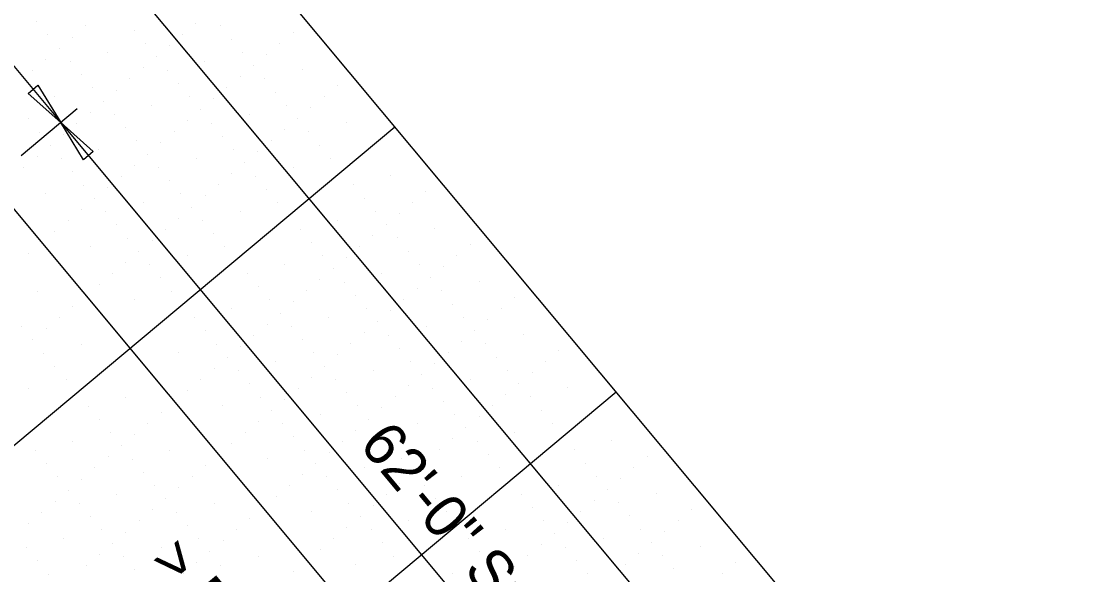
# Model space of a CAD drawing. Extents: x 2042995 to 2043795, y 305365 to 306249.
# Drawn here: x 2043429.3 to 2043490.7, y 305730.9 to 305763 of the extents above; entities that cross this region are included whole.
import ezdxf

# ---------------------------------------------------------------- set-up
doc = ezdxf.new("R2010")
doc.units = 0
for name, color, linetype in [('BR_AUTO DIMENSION', 7, 'Continuous'), ('BR_BORDER LINES', 7, 'Continuous'), ('BR_CONCRETE', 7, 'Continuous'), ('BR_GRID DOTS', 7, 'Continuous'), ('BR_GRID LINES', 7, 'Continuous'), ('BR_TEXT', 7, 'Continuous')]:
    doc.layers.add(name, color=color, linetype=linetype)

msp = doc.modelspace()

# ---------------------------------------------------------------- linework, layer by layer
at = {"layer": 'BR_AUTO DIMENSION'}
for p, q in [((2043319.917, 305903.59), (2043477.609, 305714.78)), ((2043353.357, 305850.739), (2043431.562, 305757.101)), ((2043429.275, 305755.192), (2043432.521, 305757.903)), ((2043431.562, 305757.101), (2043471.306, 305709.515))]:
    msp.add_line(p, q, dxfattribs=at)
for points in [[(2043430.247, 305759.261), (2043431.562, 305757.101), (2043429.672, 305758.78)], [(2043432.877, 305754.942), (2043431.562, 305757.101), (2043433.452, 305755.423)]]:
    msp.add_lwpolyline(points, close=True, dxfattribs=at)
at = {"layer": 'BR_BORDER LINES'}
msp.add_line((2043183.839, 306076.621), (2043615.462, 305559.826), dxfattribs=at)
at = {"layer": 'BR_CONCRETE'}
msp.add_spline([(2043139.109, 306017.548), (2043148.199, 306007.16), (2043160.233, 305993.368), (2043172.245, 305979.557), (2043184.234, 305965.727), (2043196.201, 305951.879), (2043208.145, 305938.012), (2043220.067, 305924.126), (2043231.966, 305910.221), (2043243.843, 305896.297), (2043255.698, 305882.355), (2043267.529, 305868.394), (2043279.339, 305854.414), (2043291.126, 305840.415), (2043302.89, 305826.398), (2043314.632, 305812.361), (2043326.352, 305798.306), (2043338.049, 305784.233), (2043349.724, 305770.14), (2043361.376, 305756.029), (2043373.005, 305741.899), (2043384.613, 305727.75), (2043396.197, 305713.582), (2043407.76, 305699.396), (2043419.299, 305685.191), (2043430.817, 305670.967), (2043442.311, 305656.724), (2043453.784, 305642.463), (2043465.234, 305628.182), (2043476.661, 305613.883), (2043488.066, 305599.566), (2043499.448, 305585.229), (2043510.808, 305570.874), (2043522.146, 305556.5), (2043533.461, 305542.107), (2043544.753, 305527.695), (2043547.219, 305524.543)], degree=3, dxfattribs=at)
at = {"layer": 'BR_GRID DOTS'}
for p, q in [((2043430.185, 305762.945), (2043430.185, 305762.945)), ((2043433.002, 305762.692), (2043433.002, 305762.692)), ((2043435.819, 305762.439), (2043435.819, 305762.439)), ((2043439.403, 305762.827), (2043439.403, 305762.827)), ((2043440.812, 305762.7), (2043440.812, 305762.7)), ((2043445.037, 305762.321), (2043445.037, 305762.321)), ((2043430.826, 305762.177), (2043430.826, 305762.177)), ((2043432.234, 305762.051), (2043432.234, 305762.051)), ((2043436.46, 305761.671), (2043436.46, 305761.671)), ((2043438.636, 305762.186), (2043438.636, 305762.186)), ((2043441.453, 305761.933), (2043441.453, 305761.933)), ((2043444.27, 305761.68), (2043444.27, 305761.68)), ((2043431.467, 305761.41), (2043431.467, 305761.41)), ((2043434.284, 305761.157), (2043434.284, 305761.157)), ((2043437.868, 305761.545), (2043437.868, 305761.545)), ((2043442.094, 305761.165), (2043442.094, 305761.165)), ((2043443.502, 305761.039), (2043443.502, 305761.039)), ((2043430.699, 305760.769), (2043430.699, 305760.769)), ((2043432.108, 305760.642), (2043432.108, 305760.642)), ((2043437.101, 305760.904), (2043437.101, 305760.904)), ((2043439.918, 305760.651), (2043439.918, 305760.651)), ((2043442.735, 305760.398), (2043442.735, 305760.398)), ((2043429.932, 305760.128), (2043429.932, 305760.128)), ((2043432.749, 305759.875), (2043432.749, 305759.875)), ((2043436.333, 305760.263), (2043436.333, 305760.263)), ((2043437.742, 305760.136), (2043437.742, 305760.136)), ((2043445.552, 305760.145), (2043445.552, 305760.145)), ((2043435.566, 305759.622), (2043435.566, 305759.622)), ((2043438.383, 305759.369), (2043438.383, 305759.369)), ((2043441.967, 305759.757), (2043441.967, 305759.757)), ((2043443.376, 305759.63), (2043443.376, 305759.63)), ((2043447.602, 305759.251), (2043447.602, 305759.251)), ((2043431.214, 305758.593), (2043431.214, 305758.593)), ((2043433.39, 305759.107), (2043433.39, 305759.107)), ((2043434.798, 305758.981), (2043434.798, 305758.981)), ((2043439.024, 305758.601), (2043439.024, 305758.601)), ((2043441.2, 305759.116), (2043441.2, 305759.116)), ((2043444.017, 305758.863), (2043444.017, 305758.863)), ((2043446.834, 305758.61), (2043446.834, 305758.61)), ((2043434.031, 305758.34), (2043434.031, 305758.34)), ((2043436.848, 305758.087), (2043436.848, 305758.087)), ((2043440.432, 305758.475), (2043440.432, 305758.475)), ((2043444.658, 305758.095), (2043444.658, 305758.095)), ((2043446.067, 305757.969), (2043446.067, 305757.969)), ((2043433.263, 305757.699), (2043433.263, 305757.699)), ((2043434.672, 305757.572), (2043434.672, 305757.572)), ((2043439.665, 305757.834), (2043439.665, 305757.834)), ((2043442.482, 305757.581), (2043442.482, 305757.581)), ((2043445.299, 305757.328), (2043445.299, 305757.328)), ((2043429.679, 305757.311), (2043429.679, 305757.311)), ((2043432.496, 305757.058), (2043432.496, 305757.058)), ((2043435.313, 305756.805), (2043435.313, 305756.805)), ((2043438.897, 305757.193), (2043438.897, 305757.193)), ((2043440.306, 305757.066), (2043440.306, 305757.066)), ((2043448.116, 305757.075), (2043448.116, 305757.075)), ((2043430.32, 305756.543), (2043430.32, 305756.543)), ((2043431.728, 305756.417), (2043431.728, 305756.417)), ((2043438.13, 305756.552), (2043438.13, 305756.552)), ((2043440.947, 305756.299), (2043440.947, 305756.299)), ((2043444.531, 305756.687), (2043444.531, 305756.687)), ((2043445.94, 305756.56), (2043445.94, 305756.56)), ((2043430.961, 305755.776), (2043430.961, 305755.776)), ((2043433.778, 305755.523), (2043433.778, 305755.523)), ((2043435.954, 305756.037), (2043435.954, 305756.037)), ((2043437.362, 305755.911), (2043437.362, 305755.911)), ((2043441.588, 305755.531), (2043441.588, 305755.531)), ((2043443.764, 305756.046), (2043443.764, 305756.046)), ((2043446.581, 305755.793), (2043446.581, 305755.793)), ((2043430.193, 305755.135), (2043430.193, 305755.135)), ((2043431.602, 305755.008), (2043431.602, 305755.008)), ((2043436.595, 305755.27), (2043436.595, 305755.27)), ((2043439.412, 305755.017), (2043439.412, 305755.017)), ((2043442.996, 305755.405), (2043442.996, 305755.405)), ((2043447.222, 305755.025), (2043447.222, 305755.025)), ((2043429.426, 305754.493), (2043429.426, 305754.493)), ((2043435.827, 305754.629), (2043435.827, 305754.629)), ((2043437.236, 305754.502), (2043437.236, 305754.502)), ((2043442.229, 305754.764), (2043442.229, 305754.764)), ((2043445.046, 305754.511), (2043445.046, 305754.511)), ((2043432.243, 305754.24), (2043432.243, 305754.24)), ((2043435.06, 305753.988), (2043435.06, 305753.988)), ((2043437.877, 305753.735), (2043437.877, 305753.735)), ((2043441.461, 305754.123), (2043441.461, 305754.123)), ((2043442.87, 305753.996), (2043442.87, 305753.996)), ((2043450.68, 305754.005), (2043450.68, 305754.005)), ((2043432.884, 305753.473), (2043432.884, 305753.473)), ((2043434.292, 305753.346), (2043434.292, 305753.346)), ((2043440.694, 305753.482), (2043440.694, 305753.482)), ((2043443.511, 305753.229), (2043443.511, 305753.229)), ((2043448.504, 305753.49), (2043448.504, 305753.49)), ((2043452.73, 305753.111), (2043452.73, 305753.111)), ((2043430.708, 305752.958), (2043430.708, 305752.958)), ((2043433.525, 305752.705), (2043433.525, 305752.705)), ((2043436.342, 305752.452), (2043436.342, 305752.452)), ((2043438.518, 305752.967), (2043438.518, 305752.967)), ((2043439.926, 305752.841), (2043439.926, 305752.841)), ((2043444.152, 305752.461), (2043444.152, 305752.461)), ((2043449.145, 305752.723), (2043449.145, 305752.723)), ((2043451.962, 305752.47), (2043451.962, 305752.47)), ((2043432.757, 305752.064), (2043432.757, 305752.064)), ((2043434.166, 305751.938), (2043434.166, 305751.938)), ((2043439.159, 305752.199), (2043439.159, 305752.199)), ((2043441.976, 305751.946), (2043441.976, 305751.946)), ((2043449.786, 305751.955), (2043449.786, 305751.955)), ((2043451.195, 305751.829), (2043451.195, 305751.829)), ((2043431.99, 305751.423), (2043431.99, 305751.423)), ((2043438.391, 305751.558), (2043438.391, 305751.558)), ((2043439.8, 305751.432), (2043439.8, 305751.432)), ((2043447.61, 305751.441), (2043447.61, 305751.441)), ((2043450.427, 305751.188), (2043450.427, 305751.188)), ((2043431.222, 305750.782), (2043431.222, 305750.782)), ((2043434.807, 305751.17), (2043434.807, 305751.17)), ((2043437.624, 305750.917), (2043437.624, 305750.917)), ((2043440.441, 305750.664), (2043440.441, 305750.664)), ((2043445.434, 305750.926), (2043445.434, 305750.926)), ((2043453.244, 305750.935), (2043453.244, 305750.935)), ((2043430.455, 305750.141), (2043430.455, 305750.141)), ((2043435.448, 305750.403), (2043435.448, 305750.403)), ((2043436.856, 305750.276), (2043436.856, 305750.276)), ((2043446.075, 305750.158), (2043446.075, 305750.158)), ((2043449.66, 305750.547), (2043449.66, 305750.547)), ((2043451.068, 305750.42), (2043451.068, 305750.42)), ((2043455.294, 305750.041), (2043455.294, 305750.041)), ((2043429.687, 305749.5), (2043429.687, 305749.5)), ((2043433.272, 305749.888), (2043433.272, 305749.888)), ((2043436.089, 305749.635), (2043436.089, 305749.635)), ((2043438.906, 305749.382), (2043438.906, 305749.382)), ((2043441.082, 305749.897), (2043441.082, 305749.897)), ((2043446.716, 305749.391), (2043446.716, 305749.391)), ((2043448.892, 305749.905), (2043448.892, 305749.905)), ((2043451.709, 305749.652), (2043451.709, 305749.652)), ((2043454.526, 305749.4), (2043454.526, 305749.4)), ((2043435.321, 305748.994), (2043435.321, 305748.994)), ((2043436.73, 305748.868), (2043436.73, 305748.868)), ((2043444.54, 305748.876), (2043444.54, 305748.876)), ((2043448.125, 305749.264), (2043448.125, 305749.264)), ((2043452.35, 305748.885), (2043452.35, 305748.885)), ((2043453.759, 305748.758), (2043453.759, 305748.758)), ((2043434.554, 305748.353), (2043434.554, 305748.353)), ((2043442.364, 305748.362), (2043442.364, 305748.362)), ((2043447.357, 305748.623), (2043447.357, 305748.623)), ((2043450.174, 305748.37), (2043450.174, 305748.37)), ((2043452.991, 305748.117), (2043452.991, 305748.117)), ((2043433.786, 305747.712), (2043433.786, 305747.712)), ((2043437.371, 305748.1), (2043437.371, 305748.1)), ((2043443.005, 305747.594), (2043443.005, 305747.594)), ((2043446.59, 305747.982), (2043446.59, 305747.982)), ((2043447.998, 305747.856), (2043447.998, 305747.856)), ((2043455.808, 305747.864), (2043455.808, 305747.864)), ((2043430.202, 305747.324), (2043430.202, 305747.324)), ((2043433.019, 305747.071), (2043433.019, 305747.071)), ((2043438.012, 305747.333), (2043438.012, 305747.333)), ((2043445.822, 305747.341), (2043445.822, 305747.341)), ((2043448.639, 305747.088), (2043448.639, 305747.088)), ((2043452.224, 305747.476), (2043452.224, 305747.476)), ((2043453.632, 305747.35), (2043453.632, 305747.35)), ((2043457.858, 305746.97), (2043457.858, 305746.97)), ((2043432.251, 305746.43), (2043432.251, 305746.43)), ((2043435.836, 305746.818), (2043435.836, 305746.818)), ((2043441.47, 305746.312), (2043441.47, 305746.312)), ((2043443.646, 305746.827), (2043443.646, 305746.827)), ((2043445.055, 305746.7), (2043445.055, 305746.7)), ((2043449.28, 305746.321), (2043449.28, 305746.321)), ((2043451.456, 305746.835), (2043451.456, 305746.835)), ((2043454.273, 305746.582), (2043454.273, 305746.582)), ((2043457.09, 305746.329), (2043457.09, 305746.329)), ((2043431.484, 305745.789), (2043431.484, 305745.789)), ((2043439.294, 305745.798), (2043439.294, 305745.798)), ((2043444.287, 305746.059), (2043444.287, 305746.059)), ((2043447.104, 305745.806), (2043447.104, 305745.806)), ((2043450.689, 305746.194), (2043450.689, 305746.194)), ((2043454.914, 305745.815), (2043454.914, 305745.815)), ((2043456.323, 305745.688), (2043456.323, 305745.688)), ((2043429.308, 305745.275), (2043429.308, 305745.275)), ((2043430.716, 305745.148), (2043430.716, 305745.148)), ((2043443.52, 305745.418), (2043443.52, 305745.418)), ((2043444.928, 305745.292), (2043444.928, 305745.292)), ((2043449.921, 305745.553), (2043449.921, 305745.553)), ((2043452.738, 305745.3), (2043452.738, 305745.3)), ((2043455.555, 305745.047), (2043455.555, 305745.047)), ((2043429.949, 305744.507), (2043429.949, 305744.507)), ((2043439.935, 305745.03), (2043439.935, 305745.03)), ((2043442.752, 305744.777), (2043442.752, 305744.777)), ((2043445.569, 305744.524), (2043445.569, 305744.524)), ((2043449.154, 305744.912), (2043449.154, 305744.912)), ((2043450.562, 305744.786), (2043450.562, 305744.786)), ((2043458.373, 305744.794), (2043458.373, 305744.794)), ((2043432.766, 305744.254), (2043432.766, 305744.254)), ((2043440.576, 305744.263), (2043440.576, 305744.263)), ((2043441.985, 305744.136), (2043441.985, 305744.136)), ((2043448.386, 305744.271), (2043448.386, 305744.271)), ((2043451.203, 305744.018), (2043451.203, 305744.018)), ((2043454.788, 305744.406), (2043454.788, 305744.406)), ((2043456.196, 305744.28), (2043456.196, 305744.28)), ((2043460.422, 305743.9), (2043460.422, 305743.9)), ((2043430.59, 305743.74), (2043430.59, 305743.74)), ((2043438.4, 305743.748), (2043438.4, 305743.748)), ((2043441.217, 305743.495), (2043441.217, 305743.495)), ((2043444.034, 305743.242), (2043444.034, 305743.242)), ((2043446.21, 305743.757), (2043446.21, 305743.757)), ((2043447.619, 305743.63), (2043447.619, 305743.63)), ((2043451.844, 305743.251), (2043451.844, 305743.251)), ((2043454.02, 305743.765), (2043454.02, 305743.765)), ((2043456.837, 305743.512), (2043456.837, 305743.512)), ((2043459.655, 305743.259), (2043459.655, 305743.259)), ((2043431.231, 305742.972), (2043431.231, 305742.972)), ((2043440.449, 305742.854), (2043440.449, 305742.854)), ((2043441.858, 305742.728), (2043441.858, 305742.728)), ((2043446.851, 305742.989), (2043446.851, 305742.989)), ((2043449.668, 305742.736), (2043449.668, 305742.736)), ((2043453.253, 305743.124), (2043453.253, 305743.124)), ((2043457.479, 305742.745), (2043457.479, 305742.745)), ((2043458.887, 305742.618), (2043458.887, 305742.618)), ((2043431.872, 305742.205), (2043431.872, 305742.205)), ((2043439.682, 305742.213), (2043439.682, 305742.213)), ((2043442.499, 305741.96), (2043442.499, 305741.96)), ((2043446.084, 305742.348), (2043446.084, 305742.348)), ((2043447.492, 305742.222), (2043447.492, 305742.222)), ((2043452.485, 305742.483), (2043452.485, 305742.483)), ((2043455.302, 305742.23), (2043455.302, 305742.23)), ((2043458.12, 305741.977), (2043458.12, 305741.977)), ((2043429.696, 305741.69), (2043429.696, 305741.69)), ((2043438.914, 305741.572), (2043438.914, 305741.572)), ((2043445.316, 305741.707), (2043445.316, 305741.707)), ((2043448.133, 305741.454), (2043448.133, 305741.454)), ((2043451.718, 305741.842), (2043451.718, 305741.842)), ((2043453.126, 305741.716), (2043453.126, 305741.716)), ((2043460.937, 305741.724), (2043460.937, 305741.724)), ((2043435.33, 305741.184), (2043435.33, 305741.184)), ((2043438.147, 305740.931), (2043438.147, 305740.931)), ((2043443.14, 305741.193), (2043443.14, 305741.193)), ((2043444.549, 305741.066), (2043444.549, 305741.066)), ((2043450.95, 305741.201), (2043450.95, 305741.201)), ((2043453.767, 305740.948), (2043453.767, 305740.948)), ((2043457.352, 305741.336), (2043457.352, 305741.336)), ((2043458.761, 305741.21), (2043458.761, 305741.21)), ((2043433.154, 305740.67), (2043433.154, 305740.67)), ((2043437.379, 305740.29), (2043437.379, 305740.29)), ((2043440.964, 305740.678), (2043440.964, 305740.678)), ((2043443.781, 305740.425), (2043443.781, 305740.425)), ((2043446.598, 305740.172), (2043446.598, 305740.172)), ((2043448.774, 305740.687), (2043448.774, 305740.687)), ((2043450.183, 305740.56), (2043450.183, 305740.56)), ((2043454.408, 305740.181), (2043454.408, 305740.181)), ((2043456.584, 305740.695), (2043456.584, 305740.695)), ((2043459.402, 305740.442), (2043459.402, 305740.442)), ((2043433.795, 305739.902), (2043433.795, 305739.902)), ((2043436.612, 305739.649), (2043436.612, 305739.649)), ((2043443.014, 305739.784), (2043443.014, 305739.784)), ((2043444.422, 305739.658), (2043444.422, 305739.658)), ((2043449.415, 305739.919), (2043449.415, 305739.919)), ((2043452.232, 305739.666), (2043452.232, 305739.666)), ((2043455.817, 305740.054), (2043455.817, 305740.054)), ((2043460.043, 305739.675), (2043460.043, 305739.675)), ((2043434.436, 305739.135), (2043434.436, 305739.135)), ((2043435.844, 305739.008), (2043435.844, 305739.008)), ((2043442.246, 305739.143), (2043442.246, 305739.143)), ((2043445.063, 305738.89), (2043445.063, 305738.89)), ((2043448.648, 305739.278), (2043448.648, 305739.278)), ((2043450.056, 305739.152), (2043450.056, 305739.152)), ((2043455.049, 305739.413), (2043455.049, 305739.413)), ((2043457.867, 305739.16), (2043457.867, 305739.16)), ((2043432.26, 305738.62), (2043432.26, 305738.62)), ((2043435.077, 305738.367), (2043435.077, 305738.367)), ((2043441.479, 305738.502), (2043441.479, 305738.502)), ((2043447.88, 305738.637), (2043447.88, 305738.637)), ((2043450.697, 305738.384), (2043450.697, 305738.384)), ((2043454.282, 305738.772), (2043454.282, 305738.772)), ((2043455.69, 305738.646), (2043455.69, 305738.646)), ((2043463.501, 305738.654), (2043463.501, 305738.654)), ((2043430.084, 305738.105), (2043430.084, 305738.105)), ((2043434.309, 305737.726), (2043434.309, 305737.726)), ((2043437.894, 305738.114), (2043437.894, 305738.114)), ((2043440.711, 305737.861), (2043440.711, 305737.861)), ((2043445.704, 305738.123), (2043445.704, 305738.123)), ((2043447.113, 305737.996), (2043447.113, 305737.996)), ((2043453.514, 305738.131), (2043453.514, 305738.131)), ((2043456.332, 305737.878), (2043456.332, 305737.878)), ((2043461.325, 305738.14), (2043461.325, 305738.14)), ((2043465.55, 305737.76), (2043465.55, 305737.76)), ((2043430.725, 305737.338), (2043430.725, 305737.338)), ((2043433.542, 305737.085), (2043433.542, 305737.085)), ((2043435.718, 305737.6), (2043435.718, 305737.6)), ((2043439.944, 305737.22), (2043439.944, 305737.22)), ((2043443.528, 305737.608), (2043443.528, 305737.608)), ((2043446.345, 305737.355), (2043446.345, 305737.355)), ((2043449.162, 305737.102), (2043449.162, 305737.102)), ((2043451.338, 305737.617), (2043451.338, 305737.617)), ((2043452.747, 305737.49), (2043452.747, 305737.49)), ((2043456.973, 305737.111), (2043456.973, 305737.111)), ((2043461.966, 305737.372), (2043461.966, 305737.372)), ((2043464.783, 305737.119), (2043464.783, 305737.119)), ((2043431.366, 305736.57), (2043431.366, 305736.57)), ((2043432.774, 305736.444), (2043432.774, 305736.444)), ((2043436.359, 305736.832), (2043436.359, 305736.832)), ((2043439.176, 305736.579), (2043439.176, 305736.579)), ((2043445.578, 305736.714), (2043445.578, 305736.714)), ((2043446.986, 305736.588), (2043446.986, 305736.588)), ((2043451.979, 305736.849), (2043451.979, 305736.849)), ((2043454.796, 305736.596), (2043454.796, 305736.596)), ((2043462.607, 305736.605), (2043462.607, 305736.605)), ((2043464.015, 305736.478), (2043464.015, 305736.478)), ((2043437, 305736.064), (2043437, 305736.064)), ((2043438.408, 305735.938), (2043438.408, 305735.938)), ((2043444.81, 305736.073), (2043444.81, 305736.073)), ((2043447.627, 305735.82), (2043447.627, 305735.82)), ((2043451.212, 305736.208), (2043451.212, 305736.208)), ((2043452.62, 305736.082), (2043452.62, 305736.082)), ((2043460.431, 305736.09), (2043460.431, 305736.09)), ((2043463.248, 305735.837), (2043463.248, 305735.837)), ((2043432.007, 305735.803), (2043432.007, 305735.803)), ((2043434.824, 305735.55), (2043434.824, 305735.55)), ((2043437.641, 305735.297), (2043437.641, 305735.297)), ((2043444.043, 305735.432), (2043444.043, 305735.432)), ((2043450.444, 305735.567), (2043450.444, 305735.567)), ((2043453.261, 305735.314), (2043453.261, 305735.314)), ((2043458.255, 305735.576), (2043458.255, 305735.576)), ((2043466.065, 305735.584), (2043466.065, 305735.584)), ((2043431.239, 305735.162), (2043431.239, 305735.162)), ((2043432.648, 305735.035), (2043432.648, 305735.035)), ((2043436.873, 305734.656), (2043436.873, 305734.656)), ((2043440.458, 305735.044), (2043440.458, 305735.044)), ((2043443.275, 305734.791), (2043443.275, 305734.791)), ((2043448.268, 305735.053), (2043448.268, 305735.053)), ((2043449.677, 305734.926), (2043449.677, 305734.926)), ((2043458.896, 305734.808), (2043458.896, 305734.808)), ((2043462.48, 305735.196), (2043462.48, 305735.196)), ((2043463.889, 305735.07), (2043463.889, 305735.07)), ((2043468.114, 305734.69), (2043468.114, 305734.69)), ((2043430.472, 305734.521), (2043430.472, 305734.521)), ((2043433.289, 305734.268), (2043433.289, 305734.268)), ((2043436.106, 305734.015), (2043436.106, 305734.015)), ((2043438.282, 305734.529), (2043438.282, 305734.529)), ((2043442.508, 305734.15), (2043442.508, 305734.15)), ((2043446.092, 305734.538), (2043446.092, 305734.538)), ((2043448.909, 305734.285), (2043448.909, 305734.285)), ((2043451.726, 305734.032), (2043451.726, 305734.032)), ((2043453.902, 305734.547), (2043453.902, 305734.547)), ((2043459.537, 305734.041), (2043459.537, 305734.041)), ((2043461.713, 305734.555), (2043461.713, 305734.555)), ((2043464.53, 305734.302), (2043464.53, 305734.302)), ((2043467.347, 305734.049), (2043467.347, 305734.049)), ((2043429.704, 305733.88), (2043429.704, 305733.88)), ((2043433.93, 305733.5), (2043433.93, 305733.5)), ((2043435.338, 305733.374), (2043435.338, 305733.374)), ((2043438.923, 305733.762), (2043438.923, 305733.762)), ((2043441.74, 305733.509), (2043441.74, 305733.509)), ((2043448.142, 305733.644), (2043448.142, 305733.644)), ((2043449.55, 305733.517), (2043449.55, 305733.517)), ((2043457.361, 305733.526), (2043457.361, 305733.526)), ((2043460.945, 305733.914), (2043460.945, 305733.914)), ((2043465.171, 305733.535), (2043465.171, 305733.535)), ((2043466.579, 305733.408), (2043466.579, 305733.408)), ((2043431.754, 305732.986), (2043431.754, 305732.986)), ((2043439.564, 305732.994), (2043439.564, 305732.994)), ((2043440.973, 305732.868), (2043440.973, 305732.868)), ((2043447.374, 305733.003), (2043447.374, 305733.003)), ((2043450.191, 305732.75), (2043450.191, 305732.75)), ((2043455.185, 305733.012), (2043455.185, 305733.012)), ((2043460.178, 305733.273), (2043460.178, 305733.273)), ((2043462.995, 305733.02), (2043462.995, 305733.02)), ((2043465.812, 305732.767), (2043465.812, 305732.767)), ((2043429.578, 305732.471), (2043429.578, 305732.471)), ((2043434.571, 305732.733), (2043434.571, 305732.733)), ((2043437.388, 305732.48), (2043437.388, 305732.48)), ((2043440.205, 305732.227), (2043440.205, 305732.227)), ((2043446.607, 305732.362), (2043446.607, 305732.362)), ((2043455.826, 305732.244), (2043455.826, 305732.244)), ((2043459.41, 305732.632), (2043459.41, 305732.632)), ((2043460.819, 305732.506), (2043460.819, 305732.506)), ((2043465.044, 305732.126), (2043465.044, 305732.126)), ((2043468.629, 305732.514), (2043468.629, 305732.514)), ((2043430.219, 305731.704), (2043430.219, 305731.704)), ((2043433.803, 305732.092), (2043433.803, 305732.092)), ((2043435.212, 305731.965), (2043435.212, 305731.965)), ((2043439.438, 305731.586), (2043439.438, 305731.586)), ((2043443.022, 305731.974), (2043443.022, 305731.974)), ((2043445.839, 305731.721), (2043445.839, 305731.721)), ((2043450.832, 305731.982), (2043450.832, 305731.982)), ((2043458.643, 305731.991), (2043458.643, 305731.991)), ((2043461.46, 305731.738), (2043461.46, 305731.738)), ((2043466.453, 305732), (2043466.453, 305732)), ((2043470.679, 305731.62), (2043470.679, 305731.62)), ((2043430.86, 305730.936), (2043430.86, 305730.936)), ((2043433.036, 305731.451), (2043433.036, 305731.451)), ((2043435.853, 305731.198), (2043435.853, 305731.198)), ((2043438.67, 305730.945), (2043438.67, 305730.945)), ((2043440.846, 305731.459), (2043440.846, 305731.459)), ((2043445.072, 305731.08), (2043445.072, 305731.08)), ((2043448.656, 305731.468), (2043448.656, 305731.468)), ((2043454.29, 305730.962), (2043454.29, 305730.962)), ((2043456.467, 305731.476), (2043456.467, 305731.476)), ((2043457.875, 305731.35), (2043457.875, 305731.35)), ((2043462.101, 305730.97), (2043462.101, 305730.97)), ((2043464.277, 305731.485), (2043464.277, 305731.485)), ((2043467.094, 305731.232), (2043467.094, 305731.232)), ((2043469.911, 305730.979), (2043469.911, 305730.979))]:
    msp.add_line(p, q, dxfattribs=at)
at = {"layer": 'BR_GRID LINES'}
for p, q in [((2043168.489, 306063.801), (2043600.112, 305547.005)), ((2043450.933, 305756.822), (2043297.429, 305628.617)), ((2043463.754, 305741.471), (2043310.25, 305613.266))]:
    msp.add_line(p, q, dxfattribs=at)

# ---------------------------------------------------------------- texts
at = {"layer": 'BR_AUTO DIMENSION'}
msp.add_text('62\'-0" Span 3', height=2.5, rotation=309.86836, dxfattribs=at).set_placement((2043448.799, 305738.412))
at = {"layer": 'BR_TEXT'}
msp.add_text('> End Bent 4', height=2.5, rotation=309.86836, dxfattribs=at).set_placement((2043436.63, 305731.682))

doc.saveas('drawing.dxf')
